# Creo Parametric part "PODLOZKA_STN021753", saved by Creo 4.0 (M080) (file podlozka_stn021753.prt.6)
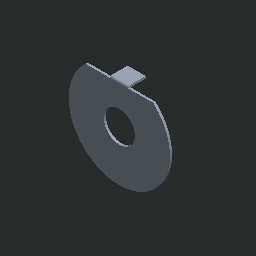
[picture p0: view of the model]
Units: millimeter Kilogram Sec (mmKs); MM, KILOGRAM, SECS
Materials in the file: OCEL_N

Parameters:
  MFG_WP_MATERIAL = "OCEL"
  NAZOV = "PODLOZKA_STN021753"
  NORMA = "STN 02 1753"
  PTC_MATERIAL_NAME = "OCEL_N"

Other parameters: HMOTNOST, HUSTOTA, D7

Created from: C021753.PRT

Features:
  1. protrusion
  2. round

Layers: 1, 2, 3, 4, 5, 6, 7, 8, 9, 10, 11, 12, 13, 14, 15, 16, 17, 18, 19, 20, 21, 22, 23, 24, 25, 26, 27, 28, 29, 30, 31, 32

Family table entries: GENERIC, PODLOZKA_4_3, PODLOZKA_STN021753, value(d_val), 2/,, value(i_val), PODLOZKA_5_3, PODLOZKA_STN021753, 2/1, PODLOZKA_6_4, PODLOZKA_STN021753, 2/2, PODLOZKA_8_4, PODLOZKA_STN021753, 2/6, PODLOZKA_10_5, PODLOZKA_STN021753, !/%, 2/:, PODLOZKA_13, PODLOZKA_STN021753, !/*, 2/>, 2/&, PODLOZKA_15, PODLOZKA_STN021753, !/., 2/@, 2/(, PODLOZKA_17, PODLOZKA_STN021753, !/1, 2/B, 2/,, PODLOZKA_19, PODLOZKA_STN021753, !/3, 2/D, 2/0, PODLOZKA_21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

Surfaces: 8 plane, 3 cylinder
